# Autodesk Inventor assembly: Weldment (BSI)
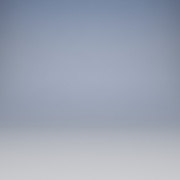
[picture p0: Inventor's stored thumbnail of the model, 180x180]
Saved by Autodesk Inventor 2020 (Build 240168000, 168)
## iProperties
Length Units: 11269
Angle Units: 11283
Time Units: 11279
Mass Units: 11290
Length Display Precision: 3
Angle Display Precision: 2
Part Number: Weldment (BSI)
Document SubType Name: Weldment
Created: 2002-06
Designer: smithga
Created: 2002-08
Designer: F.Stasiak
Weld Material: Welded Aluminum-6061
Catalog Web Link: www.expertbooks.pl
Manager: www.cadconsulting.pl
Company: Fabian Stasiak CAD Consulting
Control State: 0
Master: False
Shininess: 64.0
Angle Units: 11279
Time Units: 11290
Mass Units: 11283
Compacted: True
Density: 0.0
Volumn: 0.0
Area: 0.0
PropertySet Name: Model Information
Author: F.Stasiak
Subject: Zbiór ćwiczeń. Autodesk Inventor 2020. Kurs Professional
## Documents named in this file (1)
- M:\AUTOBUILD\M24_168_RTM\Application\App\Templates\en-US\Metric\Weldment (BSI).iam
